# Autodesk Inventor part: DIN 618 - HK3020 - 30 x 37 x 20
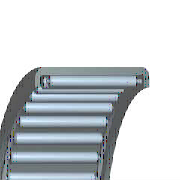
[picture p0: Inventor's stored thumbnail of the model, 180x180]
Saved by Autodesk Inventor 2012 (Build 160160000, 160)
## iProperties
Created: 2011-02
Part Number: DIN 618 - HK3020 - 30 x 37 x 20
Material: Steel, Mild
Description: Needle Roller Bearing Drawn Cup
Document SubType Name: Modeling
Standard: DIN 618
Designer: Admin
Standards Organization: DIN
Language: en-US
Size Designation: HK3020 - 30 x 37 x 20
Categories: <MemberInstance><Categories><Category DisplayName="Shaft Parts" InternalName="7f7aeb1f-a693-4053-b835-cee3144e0d98" Mnemonic="SHFT"><Category DisplayName="Beari
Density: 1 g/cm^3
IsCustomPart: 0
Author: Admin
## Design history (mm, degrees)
revolve "Body" stored, may be unused: angle "d43" = 90 deg
revolve "Groove" stored, may be unused: angle "d44" = 90 deg
revolve "Roller" stored, may be unused: angle "d48" = 90 deg
pattern_circular "Grooves" dims angle "d4" = 360 deg
body "Solid1"
sketch "Sketch"
  geometry: L1 (10, 16.312)-(10, 15.875); L2 (0.875, 17.625)-(0.875, 15); L3 (0.875, 15)-(0, 15); L4 (0, 18.5)-(20, 18.5); L5 (1.531, 16.75)-(1.531, 15.875); L6 (19.125, 17.625)-(19.125, 15); L7 (19.125, 15)-(20, 15); L8 (20, 15)-(20, 18.5); L9 (18.469, 16.75)-(18.469, 15.875); L10 (0.875, 17.625)-(19.125, 17.625); L11 (2.713, 16.312)-(2.713, 17.888); L12 (17.287, 17.888)-(17.288, 16.313); L13 (2.713, 17.888)-(17.287, 17.888); L14 (1.531, 16.75)-(18.469, 16.75); L15 (1.531, 15.875)-(18.469, 15.875); L16 (1.531, 16.312)-(18.469, 16.313); L17 (3.527, 15)-(16.473, 15); L18 (-2.4, 0)-(14.4, 0) reference; L19 (0, -0.154)-(0, 4.109) reference; A1 r 1.838 centre (4.813, 16.312) between (3.527, 17.625) and (2.975, 16.312); A2 r 1.838 centre (15.187, 16.313) between (17.025, 16.313) and (16.473, 17.625); A3 r 1.838 centre (4.813, 16.312) between (2.975, 16.312) and (3.527, 15); A4 r 1.838 centre (15.187, 16.313) between (16.473, 15) and (17.025, 16.313)
  constraints: 34 end point, 9 point on line, 8 point on circle, 5 symmetric about line, 4 centre point, 4 midpoint, 2 collinear, 1 parallel, 1 perpendicular, 7 other
  dimensions: "d0" = 1.8375 radius of A3 (= -0.7 x YM - 0.35 x WD + 0.35 x BD); "d8" = 30 diameter of L17 L18 (= WD); "d9" = 35.25 diameter of L10 L18 (= BD - 2 x YM); "d10" = 37 diameter of L4 L18 (= BD); "d11" = 33.5 diameter of L14 L18 (= -1.33333 x YM + 0.666667 x BD + 0.333333 x WD); "d12" = 35.775 diameter of L13 L18 (= -2.2 x YM + 1.1 x BD - 0.1 x WD); "d13" = 0.875 distance between parallel lines of L19 L2 (= YM); "d14" = 2.7125 distance between parallel lines of L19 L11 (= 0.35 x BD - 0.35 x WD + 0.3 x YM); "d15" = 1.53125 distance between parallel lines of L19 L5 (= 0.75 x YM + 0.125 x BD - 0.125 x WD); "d16" = 4.8125 distance from line of A1.centre L19 (= -0.5 x YM - 0.75 x WD + 0.75 x BD); "d17" = 20 distance between parallel lines of L19 L8 (= KB); "d18" = 10 distance from line of L19 L1.start (= 0.5 x KB)
fillet "Fillet1" dims "d1" = 0.65625 (= -0.25 x YM - 0.125 x WD + 0.125 x BD), "d2" = 1.53125 (= 0.125 x BD - 0.125 x WD + 0.75 x YM)
other parameters: "WD" = 30 [user parameter; used in 11 equation terms], "BD" = 37 [user parameter; used in 12 equation terms], "KB" = 20 [user parameter; used in 2 equation terms], "YM" = 0.875 [user parameter; used in 11 equation terms], "d5" = 0, "d6" = 0, "d7" = 0, "d69" = 0, "d70" = 0, "BC0" = 4.05e+07 [user parameter], "BBA" = 0 [user parameter], "KRS" = 0.8 [user parameter], "BC" = 2.16e+07 [user parameter], "BR" = 18.5 (= 0.5 x BD) [user parameter], "WR" = 15 (= 0.5 x WD) [user parameter]
